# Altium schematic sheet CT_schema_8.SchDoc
size 386 x 278 mm
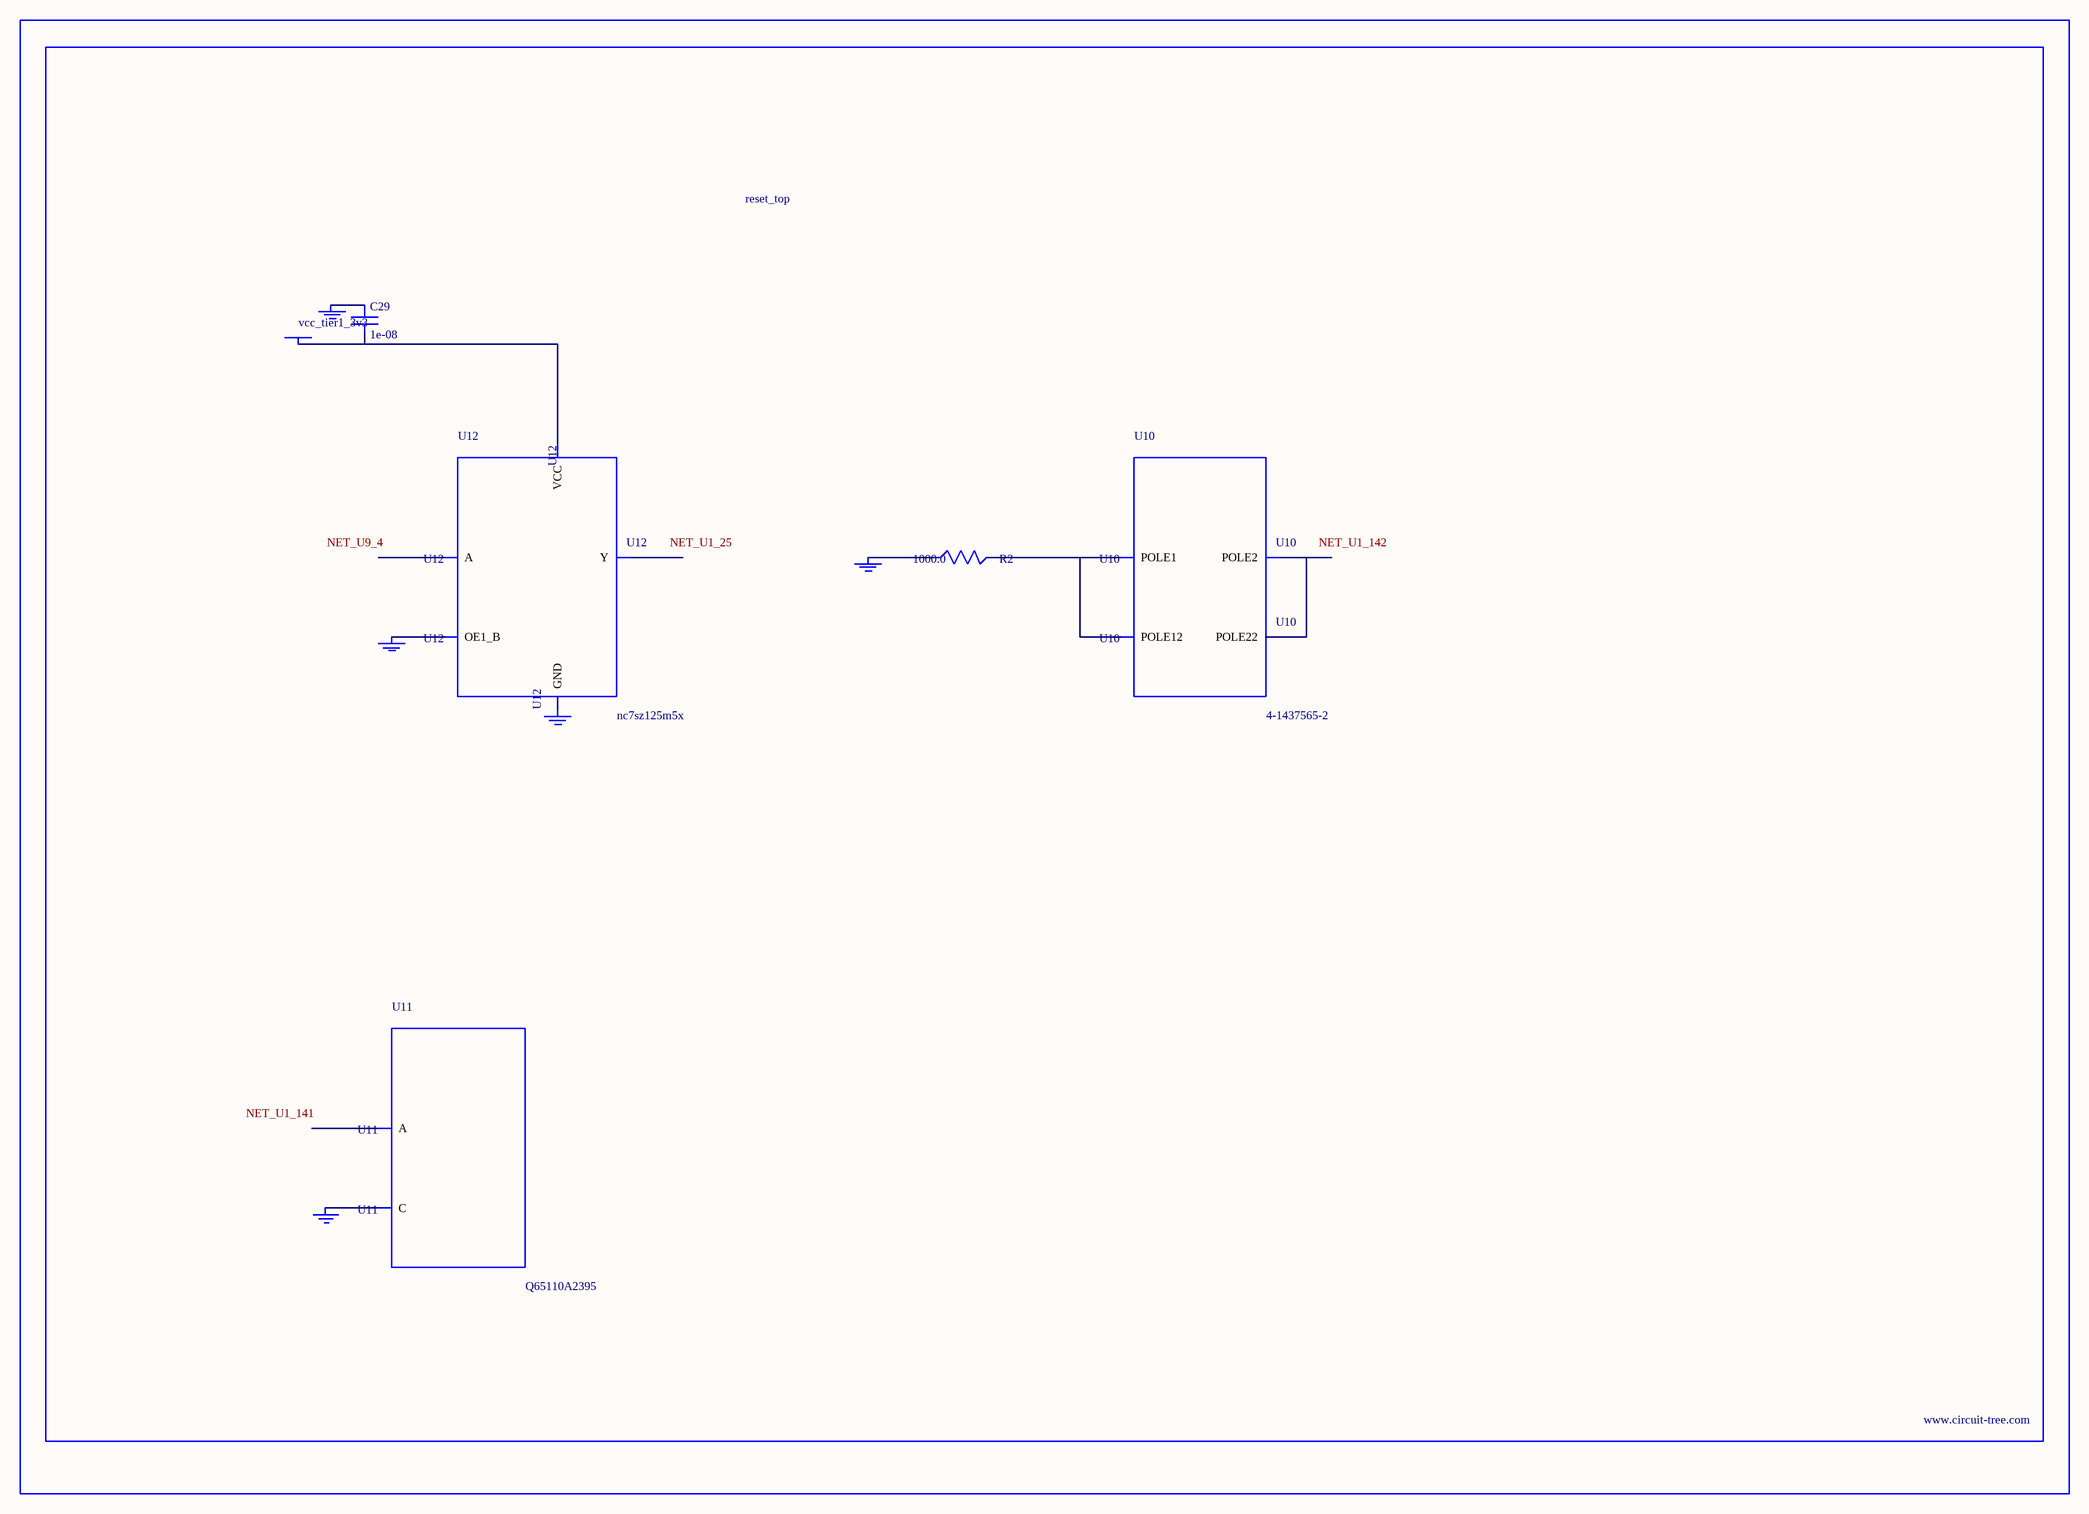
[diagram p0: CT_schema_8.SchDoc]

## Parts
BORDER7  (no value)
C29  1e-08  [C0402]
GND_INSTANCE_7_0  (no value)
GND_INSTANCE_7_1  (no value)
GND_INSTANCE_7_2  (no value)
GND_INSTANCE_7_3  (no value)
GND_INSTANCE_7_4  (no value)
POWER_INSTANCE_7_0  vcc_tier1_3v3
R2  1000.0  [R0603]
U10  4-1437565-2  [SW_4-1437565-2]
U11  Q65110A2395  [LGM67K-G1J2-24-Z]
U12  nc7sz125m5x  [NC7SZ125M5X]

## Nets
NetC29_1: C29.1 GND_INSTANCE_7_2.0(GND)
NetC29_2: C29.2 POWER_INSTANCE_7_0.0(PWR) U12.5(VCC)
NetGND_INSTANCE_7_0_0: GND_INSTANCE_7_0.0(GND) R2.1
NetGND_INSTANCE_7_1_0: GND_INSTANCE_7_1.0(GND) U11.C
NetGND_INSTANCE_7_3_0: GND_INSTANCE_7_3.0(GND) U12.1(OE1_B)
NetGND_INSTANCE_7_4_0: GND_INSTANCE_7_4.0(GND) U12.3(GND)
NetR2_2: R2.2 U10.1(POLE1) U10.2(POLE12)
NetU10_3: U10.3(POLE2) U10.4(POLE22)

Not connected (* = marked no-connect by the designer): U11 A; U12 2(A) 4(Y)

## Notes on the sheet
- Labels drawn without touching a wire or pin: NET_U1_25, NET_U1_141, NET_U1_142, NET_U9_4

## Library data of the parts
BORDER7 = BORDER_PAGE7
C29 = C0402C103K3RAC
GND_INSTANCE_7_0-GND_INSTANCE_7_4 = GND
POWER_INSTANCE_7_0 = PWR
R2 = RC0603JR-071KL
